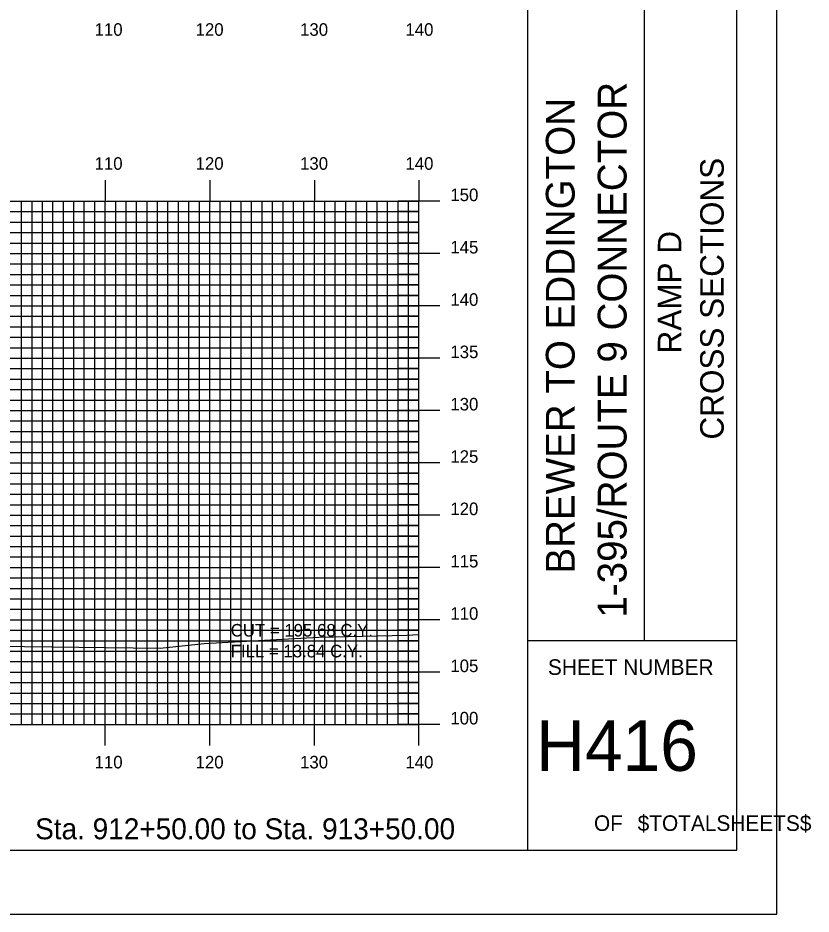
# Model space of a CAD drawing. Extents: x 860258 to 860601, y 364765 to 364985.
# Drawn here: x 860525.5 to 860601.4, y 364765.2 to 364850.8 of the extents above; entities that cross this region are included whole.
import ezdxf

# ---------------------------------------------------------------- set-up
doc = ezdxf.new("R2010")
doc.units = 0
for name, color, linetype in [('BORDER', 7, 'Continuous'), ('D_Text_Standard', 7, 'Continuous'), ('H_V ANNOTATION', 7, 'Continuous'), ('MAJOR', 7, 'Continuous'), ('MINOR', 7, 'Continuous'), ('PLOT BOUNDARY', 7, 'Continuous'), ('S_Roadway_Centerline', 7, 'Continuous')]:
    doc.layers.add(name, color=color, linetype=linetype)

msp = doc.modelspace()

# ---------------------------------------------------------------- linework, layer by layer
at = {"layer": 'BORDER'}
for p, q in [((860574.299, 364771.302), (860574.299, 364981.302)), ((860585.481, 364791.308), (860585.481, 364861.308)), ((860574.299, 364791.308), (860594.299, 364791.308))]:
    msp.add_line(p, q, dxfattribs=at)
msp.add_lwpolyline([(860274.299, 364771.302), (860594.299, 364771.302), (860594.299, 364981.302), (860274.299, 364981.302)], close=True, dxfattribs=at)
at = {"layer": 'MAJOR'}
for p, q in [((860533.899, 364835.306), (860533.899, 364833.302)), ((860543.899, 364835.306), (860543.899, 364833.302)), ((860553.899, 364835.306), (860553.899, 364833.302)), ((860563.899, 364835.306), (860563.899, 364833.302)), ((860283.899, 364833.302), (860563.899, 364833.302)), ((860283.899, 364833.302), (860563.899, 364833.302)), ((860533.899, 364783.302), (860533.899, 364833.302)), ((860543.899, 364783.302), (860543.899, 364833.302)), ((860553.899, 364783.302), (860553.899, 364833.302)), ((860565.903, 364833.302), (860561.895, 364833.302)), ((860563.899, 364783.302), (860563.899, 364833.302)), ((860563.899, 364783.302), (860563.899, 364833.302)), ((860283.899, 364828.302), (860563.899, 364828.302)), ((860565.903, 364828.302), (860561.895, 364828.302)), ((860283.899, 364823.302), (860563.899, 364823.302)), ((860565.903, 364823.302), (860561.895, 364823.302)), ((860283.899, 364818.302), (860563.899, 364818.302)), ((860565.903, 364818.302), (860561.895, 364818.302)), ((860283.899, 364813.302), (860563.899, 364813.302)), ((860565.903, 364813.302), (860561.895, 364813.302)), ((860283.899, 364808.302), (860563.899, 364808.302)), ((860565.903, 364808.302), (860561.895, 364808.302)), ((860283.899, 364803.302), (860563.899, 364803.302)), ((860565.903, 364803.302), (860561.895, 364803.302)), ((860283.899, 364798.302), (860563.899, 364798.302)), ((860565.903, 364798.302), (860561.895, 364798.302)), ((860283.899, 364793.302), (860563.899, 364793.302)), ((860565.903, 364793.302), (860561.895, 364793.302)), ((860283.899, 364788.302), (860563.899, 364788.302)), ((860565.903, 364788.302), (860561.895, 364788.302)), ((860283.899, 364783.302), (860563.899, 364783.302)), ((860283.899, 364783.302), (860563.899, 364783.302)), ((860533.899, 364781.298), (860533.899, 364783.302)), ((860543.899, 364781.298), (860543.899, 364783.302)), ((860553.899, 364781.298), (860553.899, 364783.302)), ((860565.903, 364783.302), (860561.895, 364783.302)), ((860563.899, 364781.298), (860563.899, 364783.302))]:
    msp.add_line(p, q, dxfattribs=at)
at = {"layer": 'MINOR'}
for p, q in [((860525.899, 364783.302), (860525.899, 364833.302)), ((860526.899, 364783.302), (860526.899, 364833.302)), ((860527.899, 364783.302), (860527.899, 364833.302)), ((860528.899, 364783.302), (860528.899, 364833.302)), ((860529.899, 364783.302), (860529.899, 364833.302)), ((860530.899, 364783.302), (860530.899, 364833.302)), ((860531.899, 364783.302), (860531.899, 364833.302)), ((860532.899, 364783.302), (860532.899, 364833.302)), ((860534.899, 364783.302), (860534.899, 364833.302)), ((860535.899, 364783.302), (860535.899, 364833.302)), ((860536.899, 364783.302), (860536.899, 364833.302)), ((860537.899, 364783.302), (860537.899, 364833.302)), ((860538.899, 364783.302), (860538.899, 364833.302)), ((860539.899, 364783.302), (860539.899, 364833.302)), ((860540.899, 364783.302), (860540.899, 364833.302)), ((860541.899, 364783.302), (860541.899, 364833.302)), ((860542.899, 364783.302), (860542.899, 364833.302)), ((860544.899, 364783.302), (860544.899, 364833.302)), ((860545.899, 364783.302), (860545.899, 364833.302)), ((860546.899, 364783.302), (860546.899, 364833.302)), ((860547.899, 364783.302), (860547.899, 364833.302)), ((860548.899, 364783.302), (860548.899, 364833.302)), ((860549.899, 364783.302), (860549.899, 364833.302)), ((860550.899, 364783.302), (860550.899, 364833.302)), ((860551.899, 364783.302), (860551.899, 364833.302)), ((860552.899, 364783.302), (860552.899, 364833.302)), ((860554.899, 364783.302), (860554.899, 364833.302)), ((860555.899, 364783.302), (860555.899, 364833.302)), ((860556.899, 364783.302), (860556.899, 364833.302)), ((860557.899, 364783.302), (860557.899, 364833.302)), ((860558.899, 364783.302), (860558.899, 364833.302)), ((860559.899, 364783.302), (860559.899, 364833.302)), ((860560.899, 364783.302), (860560.899, 364833.302)), ((860561.899, 364783.302), (860561.899, 364833.302)), ((860562.899, 364783.302), (860562.899, 364833.302)), ((860283.899, 364832.302), (860563.899, 364832.302)), ((860563.899, 364832.302), (860561.895, 364832.302)), ((860283.899, 364831.302), (860563.899, 364831.302)), ((860563.899, 364831.302), (860561.895, 364831.302)), ((860283.899, 364830.302), (860563.899, 364830.302)), ((860563.899, 364830.302), (860561.895, 364830.302)), ((860283.899, 364829.302), (860563.899, 364829.302)), ((860563.899, 364829.302), (860561.895, 364829.302)), ((860283.899, 364827.302), (860563.899, 364827.302)), ((860563.899, 364827.302), (860561.895, 364827.302)), ((860283.899, 364826.302), (860563.899, 364826.302)), ((860563.899, 364826.302), (860561.895, 364826.302)), ((860283.899, 364825.302), (860563.899, 364825.302)), ((860563.899, 364825.302), (860561.895, 364825.302)), ((860283.899, 364824.302), (860563.899, 364824.302)), ((860563.899, 364824.302), (860561.895, 364824.302)), ((860283.899, 364822.302), (860563.899, 364822.302)), ((860563.899, 364822.302), (860561.895, 364822.302)), ((860283.899, 364821.302), (860563.899, 364821.302)), ((860563.899, 364821.302), (860561.895, 364821.302)), ((860283.899, 364820.302), (860563.899, 364820.302)), ((860563.899, 364820.302), (860561.895, 364820.302)), ((860283.899, 364819.302), (860563.899, 364819.302)), ((860563.899, 364819.302), (860561.895, 364819.302)), ((860283.899, 364817.302), (860563.899, 364817.302)), ((860563.899, 364817.302), (860561.895, 364817.302)), ((860283.899, 364816.302), (860563.899, 364816.302)), ((860563.899, 364816.302), (860561.895, 364816.302)), ((860283.899, 364815.302), (860563.899, 364815.302)), ((860563.899, 364815.302), (860561.895, 364815.302)), ((860283.899, 364814.302), (860563.899, 364814.302)), ((860563.899, 364814.302), (860561.895, 364814.302)), ((860283.899, 364812.302), (860563.899, 364812.302)), ((860563.899, 364812.302), (860561.895, 364812.302)), ((860283.899, 364811.302), (860563.899, 364811.302)), ((860563.899, 364811.302), (860561.895, 364811.302)), ((860283.899, 364810.302), (860563.899, 364810.302)), ((860563.899, 364810.302), (860561.895, 364810.302)), ((860283.899, 364809.302), (860563.899, 364809.302)), ((860563.899, 364809.302), (860561.895, 364809.302)), ((860283.899, 364807.302), (860563.899, 364807.302)), ((860563.899, 364807.302), (860561.895, 364807.302)), ((860283.899, 364806.302), (860563.899, 364806.302)), ((860563.899, 364806.302), (860561.895, 364806.302)), ((860283.899, 364805.302), (860563.899, 364805.302)), ((860563.899, 364805.302), (860561.895, 364805.302)), ((860283.899, 364804.302), (860563.899, 364804.302)), ((860563.899, 364804.302), (860561.895, 364804.302)), ((860283.899, 364802.302), (860563.899, 364802.302)), ((860563.899, 364802.302), (860561.895, 364802.302)), ((860283.899, 364801.302), (860563.899, 364801.302)), ((860563.899, 364801.302), (860561.895, 364801.302)), ((860283.899, 364800.302), (860563.899, 364800.302)), ((860563.899, 364800.302), (860561.895, 364800.302)), ((860283.899, 364799.302), (860563.899, 364799.302)), ((860563.899, 364799.302), (860561.895, 364799.302)), ((860283.899, 364797.302), (860563.899, 364797.302)), ((860563.899, 364797.302), (860561.895, 364797.302)), ((860283.899, 364796.302), (860563.899, 364796.302)), ((860563.899, 364796.302), (860561.895, 364796.302)), ((860283.899, 364795.302), (860563.899, 364795.302)), ((860563.899, 364795.302), (860561.895, 364795.302)), ((860283.899, 364794.302), (860563.899, 364794.302)), ((860563.899, 364794.302), (860561.895, 364794.302)), ((860283.899, 364792.302), (860563.899, 364792.302)), ((860563.899, 364792.302), (860561.895, 364792.302)), ((860283.899, 364791.302), (860563.899, 364791.302)), ((860563.899, 364791.302), (860561.895, 364791.302)), ((860283.899, 364790.302), (860563.899, 364790.302)), ((860563.899, 364790.302), (860561.895, 364790.302)), ((860283.899, 364789.302), (860563.899, 364789.302)), ((860563.899, 364789.302), (860561.895, 364789.302)), ((860283.899, 364787.302), (860563.899, 364787.302)), ((860563.899, 364787.302), (860561.895, 364787.302)), ((860283.899, 364786.302), (860563.899, 364786.302)), ((860563.899, 364786.302), (860561.895, 364786.302)), ((860283.899, 364785.302), (860563.899, 364785.302)), ((860563.899, 364785.302), (860561.895, 364785.302)), ((860283.899, 364784.302), (860563.899, 364784.302)), ((860563.899, 364784.302), (860561.895, 364784.302))]:
    msp.add_line(p, q, dxfattribs=at)
at = {"layer": 'PLOT BOUNDARY'}
msp.add_lwpolyline([(860258.113, 364765.184), (860598.113, 364765.184), (860598.113, 364985.184), (860258.113, 364985.184)], close=True, dxfattribs=at)
at = {"layer": 'S_Roadway_Centerline'}
msp.add_lwpolyline([(860432, 364824.886), (860461.596, 364810.794), (860467.531, 364807.889), (860475.668, 364804.034), (860477.481, 364803.206), (860490.368, 364796.521), (860492.278, 364795.878), (860496.494, 364794.981), (860508.871, 364791.612), (860521.066, 364790.974), (860522.026, 364790.759), (860523.549, 364790.784), (860539.157, 364790.595), (860543.349, 364791.046), (860554.313, 364791.642), (860562.727, 364791.849), (860563.899, 364791.889)], dxfattribs=at)

# ---------------------------------------------------------------- texts
at = {"layer": 'BORDER'}
for s, height, p in [('1-395/ROUTE 9 CONNECTOR', 2.75575, (860583.748, 364793.502)), ('BREWER TO EDDINGTON', 2.75575, (860578.788, 364797.711)), ('CROSS SECTIONS', 2.25, (860593.04, 364810.524)), ('RAMP D', 2.25, (860588.99, 364818.752))]:
    msp.add_text(s, height=height, rotation=90, dxfattribs=at).set_placement(p)
for s, height, p in [('SHEET NUMBER', 1.49054, (860576.23, 364788.035)), ('H416', 4.8388, (860575.101, 364778.867)), ('OF', 1.4905, (860580.633, 364773.128)), ('$TOTALSHEETS$', 1.49054, (860584.812, 364773.128))]:
    msp.add_text(s, height=height, dxfattribs=at).set_placement(p)
at = {"layer": 'D_Text_Standard'}
for s, p in [('CUT = 195.68 C.Y.', (860545.899, 364791.702)), ('FILL = 13.84 C.Y.', (860545.899, 364789.71))]:
    msp.add_text(s, height=1.2, dxfattribs=at).set_placement(p)
at = {"layer": 'H_V ANNOTATION'}
for s, height, p in [('110', 1.2, (860532.883, 364849.102)), ('120', 1.2, (860542.54, 364849.102)), ('130', 1.2, (860552.529, 364849.102)), ('140', 1.2, (860562.604, 364849.102)), ('110', 1.2, (860532.883, 364836.302)), ('120', 1.2, (860542.54, 364836.302)), ('130', 1.2, (860552.529, 364836.302)), ('140', 1.2, (860562.604, 364836.302)), ('150', 1.2, (860566.899, 364833.302)), ('145', 1.2, (860566.899, 364828.302)), ('140', 1.2, (860566.899, 364823.302)), ('135', 1.2, (860566.899, 364818.302)), ('130', 1.2, (860566.899, 364813.302)), ('125', 1.2, (860566.899, 364808.302)), ('120', 1.2, (860566.899, 364803.302)), ('115', 1.2, (860566.899, 364798.302)), ('110', 1.2, (860566.899, 364793.302)), ('105', 1.2, (860566.899, 364788.302)), ('100', 1.2, (860566.899, 364783.302)), ('110', 1.2, (860532.883, 364779.102)), ('120', 1.2, (860542.54, 364779.102)), ('130', 1.2, (860552.529, 364779.102)), ('140', 1.2, (860562.604, 364779.102)), ('Sta. 912+50.00 to Sta. 913+50.00', 2.0004, (860527.196, 364772.332))]:
    msp.add_text(s, height=height, dxfattribs=at).set_placement(p)

doc.saveas('drawing.dxf')
